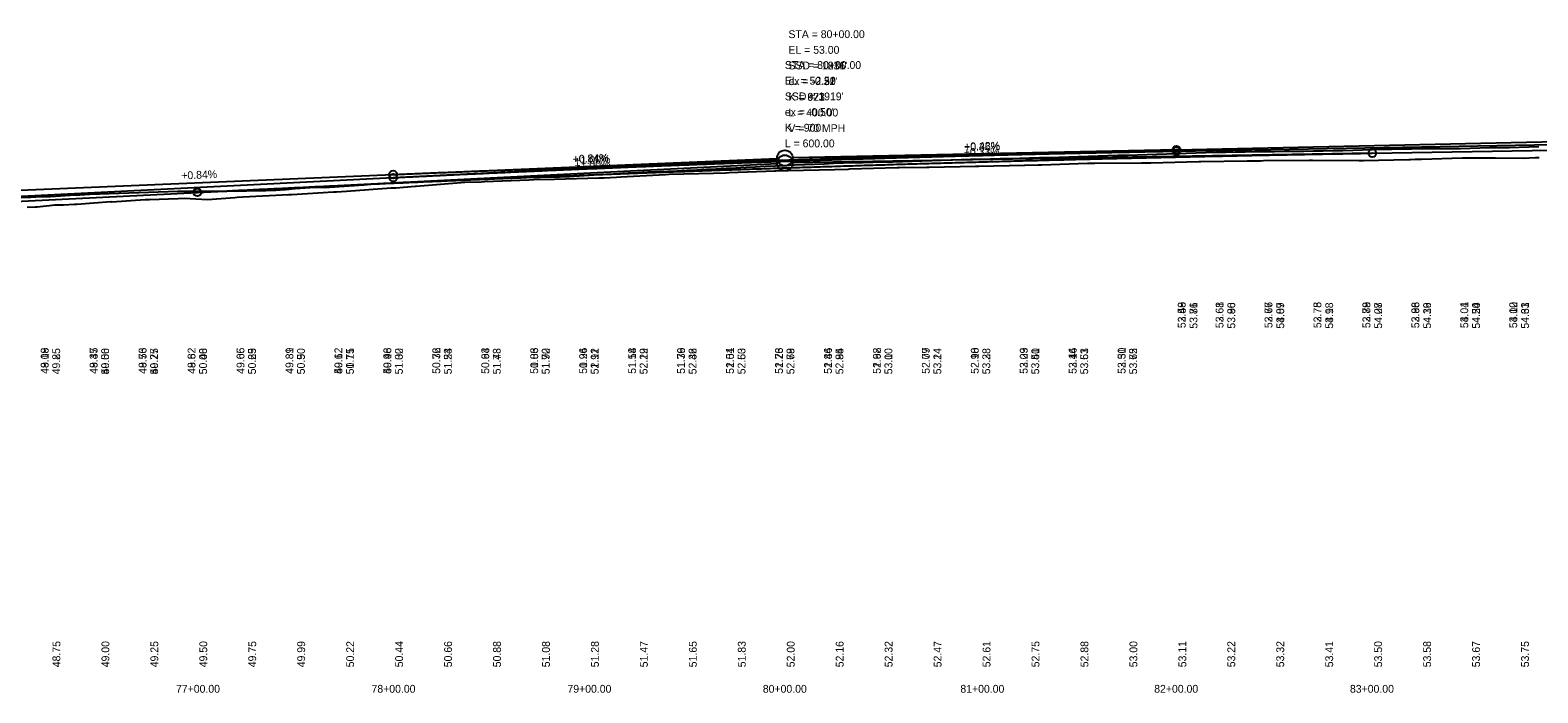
# Model space of a CAD drawing. Extents: x 3880794 to 3915434, y 287517 to 300173.
# Drawn here: x 3888153 to 3888923, y 296520 to 296858 of the extents above; entities that cross this region are included whole.
import ezdxf

# ---------------------------------------------------------------- set-up
doc = ezdxf.new("R2010")
doc.units = 0
for name, color, linetype in [('Level 1', 7, 'Continuous'), ('Level 2', 7, 'Continuous'), ('Level 30', 7, 'Continuous'), ('Level 31', 7, 'Continuous'), ('Level 32', 7, 'Continuous')]:
    doc.layers.add(name, color=color, linetype=linetype)

msp = doc.modelspace()

# ---------------------------------------------------------------- linework, layer by layer
at = {"layer": 'Level 1'}
for p, q in [((3888738.3, 296796.31), (3889688.3, 296813.2)), ((3888838.3, 296795.26), (3889488.3, 296806.09)), ((3888338.3, 296782.76), (3888534.3, 296792.56)), ((3888738.3, 296796.31), (3888542.3, 296792.83)), ((3888838.3, 296795.26), (3888542.3, 296790.32)), ((3888238.3, 296775.26), (3888534.3, 296790.06)), ((3888138.3, 296772.76), (3888338.3, 296782.76)), ((3888138.3, 296770.26), (3888238.3, 296775.26))]:
    msp.add_line(p, q, dxfattribs=at)
for points in [[(3888213.77, 296771.54), (3888228.46, 296772.14), (3888231.56, 296772.27), (3888243.46, 296771.57), (3888257.41, 296772.69), (3888258.68, 296772.75), (3888261.5, 296772.9), (3888284.97, 296774.13), (3888286.46, 296774.17), (3888307.75, 296775.47), (3888309.37, 296775.58), (3888314.47, 296775.93), (3888337.33, 296777.49), (3888339.57, 296777.64), (3888349.44, 296778.45), (3888350.03, 296778.49), (3888372.84, 296780.35), (3888374.91, 296780.39), (3888383.28, 296780.69), (3888384.96, 296780.85), (3888407.59, 296781.69), (3888410.04, 296781.81), (3888420.58, 296782.06), (3888443.34, 296782.6), (3888445.58, 296782.64), (3888446.03, 296782.65), (3888452.37, 296783.02), (3888454.51, 296783.14), (3888477.27, 296784.45), (3888479.27, 296784.48), (3888501.82, 296785.05), (3888508.1, 296785.3), (3888509.82, 296785.34), (3888533.14, 296786.26), (3888533.67, 296786.28), (3888538.47, 296786.39), (3888539.94, 296786.43), (3888563.67, 296786.97), (3888570.71, 296787.17), (3888571.55, 296787.22), (3888595.63, 296787.88), (3888596.7, 296787.91), (3888610.74, 296788.16), (3888611.98, 296788.17), (3888635.7, 296788.6), (3888637.29, 296788.63), (3888660.48, 296789.14), (3888660.86, 296789.15), (3888667.71, 296789.36), (3888669.32, 296789.38), (3888692.9, 296790.11), (3888695.23, 296790.13), (3888696.68, 296790.12), (3888720.41, 296790.3), (3888724.32, 296790.39), (3888725.18, 296790.4), (3888749.66, 296790.95), (3888750.77, 296790.97), (3888774.45, 296791.36), (3888781.24, 296791.42), (3888782.73, 296791.49), (3888806.24, 296791.72), (3888807.7, 296791.71), (3888831.41, 296791.52), (3888831.99, 296791.58), (3888832.85, 296791.6), (3888833.74, 296791.58), (3888856.89, 296792.08), (3888857.87, 296792.1), (3888860.16, 296792.19), (3888861.46, 296792.18), (3888863.36, 296792.15), (3888884.3, 296792.87), (3888887.58, 296792.95), (3888894.96, 296792.83), (3888901.15, 296792.94), (3888915.31, 296792.72), (3888921.69, 296793.05), (3888923.47, 296792.97)], [(3888151.4, 296767.63), (3888155.49, 296767.82), (3888156.52, 296767.94), (3888161.02, 296768.35), (3888162.78, 296768.59), (3888165.44, 296768.96), (3888167.71, 296768.85), (3888168.39, 296768.88), (3888169.57, 296768.85), (3888169.87, 296768.86), (3888175.48, 296769.17), (3888175.94, 296769.22), (3888176.69, 296769.29), (3888194.04, 296770.52), (3888194.67, 296770.46), (3888211.62, 296771.54), (3888213.77, 296771.54)]]:
    msp.add_lwpolyline(points, dxfattribs=at)
for centre in [(3888538.3, 296792.76), (3888538.3, 296790.26)]:
    msp.add_circle(centre, 4, dxfattribs=at)
for points in [[(3888238.3, 296775.26), (3888250.3, 296775.85), (3888262.3, 296776.44), (3888274.3, 296777.02), (3888286.3, 296777.59), (3888298.3, 296778.16), (3888310.3, 296778.71), (3888322.3, 296779.26), (3888334.3, 296779.8), (3888346.3, 296780.33), (3888358.3, 296780.86), (3888370.3, 296781.37), (3888382.3, 296781.88), (3888394.3, 296782.38), (3888406.3, 296782.87), (3888418.3, 296783.36), (3888430.3, 296783.83), (3888442.3, 296784.3), (3888454.3, 296784.76), (3888466.3, 296785.21), (3888478.3, 296785.66), (3888490.3, 296786.09), (3888502.3, 296786.52), (3888514.3, 296786.94), (3888526.3, 296787.35), (3888538.3, 296787.76), (3888550.3, 296788.15), (3888562.3, 296788.54), (3888574.3, 296788.92), (3888586.3, 296789.29), (3888598.3, 296789.66), (3888610.3, 296790.01), (3888622.3, 296790.36), (3888634.3, 296790.7), (3888646.3, 296791.03), (3888658.3, 296791.36), (3888670.3, 296791.67), (3888682.3, 296791.98), (3888694.3, 296792.28), (3888706.3, 296792.57), (3888718.3, 296792.86), (3888730.3, 296793.13), (3888742.3, 296793.4), (3888754.3, 296793.66), (3888766.3, 296793.91), (3888778.3, 296794.16), (3888790.3, 296794.39), (3888802.3, 296794.62), (3888814.3, 296794.84), (3888826.3, 296795.05), (3888838.3, 296795.26)], [(3888338.3, 296782.76), (3888346.3, 296783.15), (3888354.3, 296783.55), (3888362.3, 296783.93), (3888370.3, 296784.32), (3888378.3, 296784.69), (3888386.3, 296785.06), (3888394.3, 296785.43), (3888402.3, 296785.79), (3888410.3, 296786.15), (3888418.3, 296786.5), (3888426.3, 296786.85), (3888434.3, 296787.19), (3888442.3, 296787.52), (3888450.3, 296787.85), (3888458.3, 296788.18), (3888466.3, 296788.5), (3888474.3, 296788.81), (3888482.3, 296789.12), (3888490.3, 296789.43), (3888498.3, 296789.73), (3888506.3, 296790.02), (3888514.3, 296790.31), (3888522.3, 296790.59), (3888530.3, 296790.87), (3888538.3, 296791.15), (3888546.3, 296791.41), (3888554.3, 296791.68), (3888562.3, 296791.94), (3888570.3, 296792.19), (3888578.3, 296792.44), (3888586.3, 296792.68), (3888594.3, 296792.92), (3888602.3, 296793.15), (3888610.3, 296793.38), (3888618.3, 296793.6), (3888626.3, 296793.82), (3888634.3, 296794.03), (3888642.3, 296794.23), (3888650.3, 296794.44), (3888658.3, 296794.63), (3888666.3, 296794.82), (3888674.3, 296795.01), (3888682.3, 296795.19), (3888690.3, 296795.37), (3888698.3, 296795.54), (3888706.3, 296795.7), (3888714.3, 296795.86), (3888722.3, 296796.02), (3888730.3, 296796.17), (3888738.3, 296796.31)]]:
    msp.add_spline(points, degree=3, dxfattribs=at)
at = {"layer": 'Level 2'}
for p, q in [((3888738.3, 296797.04), (3889538.3, 296814.17)), ((3888338.3, 296784.36), (3888534.3, 296792.59)), ((3888738.3, 296797.04), (3888542.3, 296792.84)), ((3886763.3, 296718.25), (3888338.3, 296784.36))]:
    msp.add_line(p, q, dxfattribs=at)
for points in [[(3888538.3, 296789.05), (3888543.3, 296789.24), (3888548.3, 296789.43), (3888553.3, 296789.64), (3888558.3, 296789.86), (3888563.3, 296790.08), (3888568.3, 296790.26), (3888573.3, 296790.45), (3888578.3, 296790.52), (3888583.3, 296790.65), (3888588.3, 296790.86), (3888593.3, 296790.91), (3888598.3, 296790.95), (3888603.3, 296791.11), (3888608.3, 296791.36), (3888613.3, 296791.59), (3888618.3, 296791.73), (3888623.3, 296791.87), (3888628.3, 296791.99), (3888633.3, 296792.12), (3888638.3, 296792.26), (3888643.3, 296792.39), (3888648.3, 296792.53), (3888653.3, 296792.6), (3888658.3, 296792.75), (3888663.3, 296792.92), (3888668.3, 296793.03), (3888673.3, 296793.1), (3888678.3, 296793.19), (3888683.3, 296793.36), (3888688.3, 296793.54), (3888693.3, 296793.7), (3888698.3, 296793.85), (3888703.3, 296794), (3888708.3, 296794.16), (3888713.3, 296794.32), (3888718.3, 296794.49), (3888723.3, 296794.66), (3888728.3, 296794.82), (3888733.3, 296794.99), (3888738.3, 296795.15), (3888743.3, 296795.32), (3888748.3, 296795.48), (3888753.3, 296795.64), (3888758.3, 296795.75), (3888763.3, 296795.83), (3888768.3, 296795.92), (3888773.3, 296796), (3888778.3, 296796.09), (3888783.3, 296796.05), (3888788.3, 296796.13), (3888793.3, 296796.21), (3888798.3, 296796.26), (3888803.3, 296796.31), (3888808.3, 296796.38), (3888813.3, 296796.48), (3888818.3, 296796.6), (3888823.3, 296796.7), (3888828.3, 296796.8), (3888833.3, 296796.96), (3888838.3, 296797.19), (3888843.3, 296797.3), (3888848.3, 296797.38), (3888853.3, 296797.47), (3888858.3, 296797.52), (3888863.3, 296797.57), (3888868.3, 296797.62), (3888873.3, 296797.67), (3888878.3, 296797.69), (3888883.3, 296797.69), (3888888.3, 296797.82), (3888893.3, 296797.95), (3888898.3, 296798.09), (3888903.3, 296798.11), (3888908.3, 296798.21), (3888913.3, 296798.37), (3888918.3, 296798.55), (3888923.3, 296798.74)], [(3888148.3, 296772.61), (3888153.3, 296772.86), (3888158.3, 296773.1), (3888163.3, 296773.21), (3888168.3, 296773.48), (3888173.3, 296773.74), (3888178.3, 296774.02), (3888183.3, 296774.31), (3888188.3, 296774.49), (3888193.3, 296774.66), (3888198.3, 296774.84), (3888203.3, 296775.01), (3888208.3, 296775.2), (3888213.3, 296775.39), (3888218.3, 296775.59), (3888223.3, 296775.77), (3888228.3, 296775.85), (3888233.3, 296775.87), (3888238.3, 296775.88), (3888243.3, 296775.9), (3888248.3, 296775.91), (3888253.3, 296775.93), (3888258.3, 296775.98), (3888263.3, 296776.08), (3888268.3, 296776.17), (3888273.3, 296776.27), (3888278.3, 296776.37), (3888283.3, 296776.77), (3888288.3, 296777.2), (3888293.3, 296777.58), (3888298.3, 296777.96), (3888303.3, 296777.71), (3888308.3, 296778.12), (3888313.3, 296778.36), (3888318.3, 296778.69), (3888323.3, 296779.16), (3888328.3, 296779.63), (3888333.3, 296779.92), (3888338.3, 296780.16), (3888343.3, 296780.39), (3888348.3, 296780.64), (3888353.3, 296780.88), (3888358.3, 296781.12), (3888363.3, 296781.36), (3888368.3, 296781.6), (3888373.3, 296781.84), (3888378.3, 296782.08), (3888383.3, 296782.27), (3888388.3, 296782.43), (3888393.3, 296782.54), (3888398.3, 296782.63), (3888403.3, 296782.79), (3888408.3, 296782.95), (3888413.3, 296783.05), (3888418.3, 296783.13), (3888423.3, 296783.22), (3888428.3, 296783.43), (3888433.3, 296783.73), (3888438.3, 296784.05), (3888443.3, 296784.31), (3888448.3, 296784.52), (3888453.3, 296784.81), (3888458.3, 296785.14), (3888463.3, 296785.46), (3888468.3, 296785.71), (3888473.3, 296785.91), (3888478.3, 296786.11), (3888483.3, 296786.3), (3888488.3, 296786.55), (3888493.3, 296786.8), (3888498.3, 296787.05), (3888503.3, 296787.32), (3888508.3, 296787.57), (3888513.3, 296787.82), (3888518.3, 296788.08), (3888523.3, 296788.34), (3888528.3, 296788.61), (3888533.3, 296788.83), (3888538.3, 296789.05)]]:
    msp.add_lwpolyline(points, dxfattribs=at)
for centre, radius in [((3888538.3, 296792.76), 4), ((3888738.3, 296797.04), 2), ((3888338.3, 296784.36), 2)]:
    msp.add_circle(centre, radius, dxfattribs=at)
msp.add_spline([(3888338.3, 296784.36), (3888346.3, 296784.7), (3888354.3, 296785.03), (3888362.3, 296785.35), (3888370.3, 296785.68), (3888378.3, 296786), (3888386.3, 296786.32), (3888394.3, 296786.63), (3888402.3, 296786.94), (3888410.3, 296787.25), (3888418.3, 296787.56), (3888426.3, 296787.86), (3888434.3, 296788.15), (3888442.3, 296788.45), (3888450.3, 296788.74), (3888458.3, 296789.03), (3888466.3, 296789.31), (3888474.3, 296789.6), (3888482.3, 296789.87), (3888490.3, 296790.15), (3888498.3, 296790.42), (3888506.3, 296790.69), (3888514.3, 296790.95), (3888522.3, 296791.22), (3888530.3, 296791.47), (3888538.3, 296791.73), (3888546.3, 296791.98), (3888554.3, 296792.23), (3888562.3, 296792.47), (3888570.3, 296792.72), (3888578.3, 296792.96), (3888586.3, 296793.19), (3888594.3, 296793.42), (3888602.3, 296793.65), (3888610.3, 296793.88), (3888618.3, 296794.1), (3888626.3, 296794.32), (3888634.3, 296794.54), (3888642.3, 296794.75), (3888650.3, 296794.96), (3888658.3, 296795.16), (3888666.3, 296795.37), (3888674.3, 296795.56), (3888682.3, 296795.76), (3888690.3, 296795.95), (3888698.3, 296796.14), (3888706.3, 296796.33), (3888714.3, 296796.51), (3888722.3, 296796.69), (3888730.3, 296796.87), (3888738.3, 296797.04)], degree=3, dxfattribs=at)
at = {"layer": 'Level 31'}
for centre in [(3888738.3, 296796.31), (3888838.3, 296795.26), (3888238.3, 296775.26), (3888338.3, 296782.76)]:
    msp.add_circle(centre, 2, dxfattribs=at)

# ---------------------------------------------------------------- texts
at = {"layer": 'Level 2'}
for s, p in [('STA = 80+00.00', (3888540.14, 296854.02)), ('EL = 53.00', (3888540.14, 296846.02)), ("SSD = 1816'", (3888540.14, 296838.02)), ("ex = -0.21'", (3888540.14, 296830.02)), ('K = 973', (3888540.14, 296822.02)), ('L = 400.00', (3888540.14, 296814.02)), ('V = 70 MPH', (3888540.14, 296806.02)), ('77+00.00', (3888227.37, 296519.76)), ('78+00.00', (3888327.21, 296519.76)), ('79+00.00', (3888427.27, 296519.76)), ('80+00.00', (3888527.05, 296519.76)), ('81+00.00', (3888627.94, 296519.76)), ('82+00.00', (3888726.93, 296519.76)), ('83+00.00', (3888826.9, 296519.76))]:
    msp.add_text(s, height=4, dxfattribs=at).set_placement(p)
for s, rotation, p in [('+0.43%', 1.2269, (3888629.92, 296796.72)), ('+0.84%', 2.4036, (3888429.98, 296790.21)), ('+0.84%', 2.4036, (3888430.15, 296790.22)), ('+0.84%', 2.4036, (3888230.15, 296781.83)), ('53.86', 90, (3888748.99, 296705.66)), ('53.96', 90, (3888768.3, 296705.66)), ('54.07', 90, (3888793.3, 296705.66)), ('54.18', 90, (3888818.3, 296705.66)), ('54.28', 90, (3888843.3, 296705.66)), ('54.39', 90, (3888868.3, 296705.66)), ('54.50', 90, (3888893.3, 296705.66)), ('54.61', 90, (3888918.3, 296705.66)), ('49.85', 90, (3888168.18, 296682.34)), ('50.06', 90, (3888193.18, 296682.34)), ('50.27', 90, (3888218.18, 296682.34)), ('50.48', 90, (3888243.18, 296682.34)), ('50.69', 90, (3888268.18, 296682.34)), ('50.90', 90, (3888293.18, 296682.34)), ('51.11', 90, (3888318.18, 296682.34)), ('51.32', 90, (3888343.18, 296682.34)), ('51.53', 90, (3888368.18, 296682.34)), ('51.73', 90, (3888393.18, 296682.34)), ('51.92', 90, (3888418.18, 296682.34)), ('52.11', 90, (3888443.18, 296682.34)), ('52.29', 90, (3888468.18, 296682.34)), ('52.46', 90, (3888493.18, 296682.34)), ('52.63', 90, (3888518.18, 296682.34)), ('52.79', 90, (3888543.18, 296682.34)), ('52.95', 90, (3888568.18, 296682.34)), ('53.10', 90, (3888593.18, 296682.34)), ('53.24', 90, (3888618.18, 296682.34)), ('53.38', 90, (3888643.18, 296682.34)), ('53.51', 90, (3888668.18, 296682.34)), ('53.63', 90, (3888693.18, 296682.34)), ('53.75', 90, (3888718.18, 296682.34))]:
    msp.add_text(s, height=4, rotation=rotation, dxfattribs=at).set_placement(p)
at = {"layer": 'Level 30'}
for s, p in [('52.59', (3888742.99, 296705.91)), ('52.68', (3888762.3, 296705.91)), ('52.76', (3888787.3, 296705.91)), ('52.78', (3888812.3, 296705.91)), ('52.78', (3888837.3, 296705.91)), ('52.88', (3888862.3, 296705.91)), ('53.04', (3888887.3, 296705.91)), ('53.00', (3888912.3, 296705.91)), ('48.18', (3888162.3, 296682.58)), ('48.47', (3888187.3, 296682.58)), ('48.76', (3888212.3, 296682.58)), ('48.82', (3888237.3, 296682.58)), ('49.05', (3888262.3, 296682.58)), ('49.31', (3888287.3, 296682.58)), ('49.62', (3888312.3, 296682.58)), ('49.96', (3888337.3, 296682.58)), ('50.36', (3888362.3, 296682.58)), ('50.64', (3888387.3, 296682.58)), ('50.83', (3888412.3, 296682.58)), ('50.94', (3888437.3, 296682.58)), ('51.18', (3888462.3, 296682.58)), ('51.39', (3888487.3, 296682.58)), ('51.54', (3888512.3, 296682.58)), ('51.73', (3888537.3, 296682.58)), ('51.84', (3888562.3, 296682.58)), ('51.98', (3888587.3, 296682.58)), ('52.09', (3888612.3, 296682.58)), ('52.18', (3888637.3, 296682.58)), ('52.29', (3888662.3, 296682.58)), ('52.44', (3888687.3, 296682.58)), ('52.50', (3888712.3, 296682.58))]:
    msp.add_text(s, height=4, rotation=90, dxfattribs=at).set_placement(p)
for s, p in [('77+00.00', (3888227.37, 296519.76)), ('77+00.00', (3888227.37, 296519.76)), ('77+00.00', (3888227.37, 296519.76)), ('78+00.00', (3888327.21, 296519.76)), ('78+00.00', (3888327.21, 296519.76)), ('78+00.00', (3888327.21, 296519.76)), ('79+00.00', (3888427.27, 296519.76)), ('79+00.00', (3888427.27, 296519.76)), ('79+00.00', (3888427.27, 296519.76)), ('80+00.00', (3888527.05, 296519.76)), ('80+00.00', (3888527.05, 296519.76)), ('80+00.00', (3888527.05, 296519.76)), ('81+00.00', (3888627.94, 296519.76)), ('81+00.00', (3888627.94, 296519.76)), ('81+00.00', (3888627.94, 296519.76)), ('82+00.00', (3888726.93, 296519.76)), ('82+00.00', (3888726.93, 296519.76)), ('82+00.00', (3888726.93, 296519.76)), ('83+00.00', (3888826.9, 296519.76)), ('83+00.00', (3888826.9, 296519.76)), ('83+00.00', (3888826.9, 296519.76))]:
    msp.add_text(s, height=4, dxfattribs=at).set_placement(p)
at = {"layer": 'Level 31'}
for s, p in [('STA = 80+00.00', (3888540.14, 296854.02)), ('EL = 53.00', (3888540.14, 296846.02)), ('STA = 80+00.00', (3888538.3, 296838.26)), ("SSD = 1231'", (3888540.14, 296838.02)), ('EL = 52.50', (3888538.3, 296830.26)), ("ex = -0.32'", (3888540.14, 296830.02)), ("SSD = 1919'", (3888538.3, 296822.26)), ('K = 621', (3888540.14, 296822.02)), ("ex = -0.50'", (3888538.3, 296814.26)), ('L = 400.00', (3888540.14, 296814.02)), ('K = 900', (3888538.3, 296806.26)), ('V = 70 MPH', (3888540.14, 296806.02)), ('L = 600.00', (3888538.3, 296798.26))]:
    msp.add_text(s, height=4, dxfattribs=at).set_placement(p)
for s, rotation, p in [('+0.36%', 1.01848, (3888629.93, 296796.39)), ('+1.00%', 2.86241, (3888430.99, 296789.4)), ('+0.33%', 0.95484, (3888629.71, 296793.78)), ('+1.00%', 2.86241, (3888430.99, 296786.9)), ('53.71', 90, (3888748.99, 296705.66)), ('53.80', 90, (3888768.3, 296705.66)), ('53.89', 90, (3888793.3, 296705.66)), ('53.98', 90, (3888818.3, 296705.66)), ('54.07', 90, (3888843.3, 296705.66)), ('54.16', 90, (3888868.3, 296705.66)), ('54.24', 90, (3888893.3, 296705.66)), ('54.33', 90, (3888918.3, 296705.66)), ('49.25', 90, (3888168.18, 296682.34)), ('49.50', 90, (3888193.18, 296682.34)), ('49.75', 90, (3888218.18, 296682.34)), ('50.00', 90, (3888243.18, 296682.34)), ('50.25', 90, (3888268.18, 296682.34)), ('50.50', 90, (3888293.18, 296682.34)), ('50.75', 90, (3888318.18, 296682.34)), ('51.00', 90, (3888343.18, 296682.34)), ('51.24', 90, (3888368.18, 296682.34)), ('51.48', 90, (3888393.18, 296682.34)), ('51.70', 90, (3888418.18, 296682.34)), ('51.92', 90, (3888443.18, 296682.34)), ('52.12', 90, (3888468.18, 296682.34)), ('52.32', 90, (3888493.18, 296682.34)), ('52.50', 90, (3888518.18, 296682.34)), ('52.68', 90, (3888543.18, 296682.34)), ('52.84', 90, (3888568.18, 296682.34)), ('53.00', 90, (3888593.18, 296682.34)), ('53.14', 90, (3888618.18, 296682.34)), ('53.28', 90, (3888643.18, 296682.34)), ('53.40', 90, (3888668.18, 296682.34)), ('53.51', 90, (3888693.18, 296682.34)), ('53.62', 90, (3888718.18, 296682.34)), ('48.75', 90, (3888168.3, 296532.76)), ('49.00', 90, (3888193.3, 296532.76)), ('49.25', 90, (3888218.3, 296532.76)), ('49.50', 90, (3888243.3, 296532.76)), ('49.75', 90, (3888268.3, 296532.76)), ('49.99', 90, (3888293.3, 296532.76)), ('50.22', 90, (3888318.3, 296532.76)), ('50.44', 90, (3888343.3, 296532.76)), ('50.66', 90, (3888368.3, 296532.76)), ('50.88', 90, (3888393.3, 296532.76)), ('51.08', 90, (3888418.3, 296532.76)), ('51.28', 90, (3888443.3, 296532.76)), ('51.47', 90, (3888468.3, 296532.76)), ('51.65', 90, (3888493.3, 296532.76)), ('51.83', 90, (3888518.3, 296532.76)), ('52.00', 90, (3888543.3, 296532.76)), ('52.16', 90, (3888568.3, 296532.76)), ('52.32', 90, (3888593.3, 296532.76)), ('52.47', 90, (3888618.3, 296532.76)), ('52.61', 90, (3888643.3, 296532.76)), ('52.75', 90, (3888668.3, 296532.76)), ('52.88', 90, (3888693.3, 296532.76)), ('53.00', 90, (3888718.3, 296532.76)), ('53.11', 90, (3888743.3, 296532.76)), ('53.22', 90, (3888768.3, 296532.76)), ('53.32', 90, (3888793.3, 296532.76)), ('53.41', 90, (3888818.3, 296532.76)), ('53.50', 90, (3888843.3, 296532.76)), ('53.58', 90, (3888868.3, 296532.76)), ('53.67', 90, (3888893.3, 296532.76)), ('53.75', 90, (3888918.3, 296532.76))]:
    msp.add_text(s, height=4, rotation=rotation, dxfattribs=at).set_placement(p)
at = {"layer": 'Level 32'}
for s, p in [('53.48', (3888742.99, 296705.91)), ('53.61', (3888762.3, 296705.91)), ('53.67', (3888787.3, 296705.91)), ('53.75', (3888812.3, 296705.91)), ('53.89', (3888837.3, 296705.91)), ('53.96', (3888862.3, 296705.91)), ('54.01', (3888887.3, 296705.91)), ('54.12', (3888912.3, 296705.91)), ('49.09', (3888162.3, 296682.58)), ('49.35', (3888187.3, 296682.58)), ('49.53', (3888212.3, 296682.58)), ('49.62', (3888237.3, 296682.58)), ('49.66', (3888262.3, 296682.58)), ('49.89', (3888287.3, 296682.58)), ('50.12', (3888312.3, 296682.58)), ('50.48', (3888337.3, 296682.58)), ('50.72', (3888362.3, 296682.58)), ('50.93', (3888387.3, 296682.58)), ('51.06', (3888412.3, 296682.58)), ('51.26', (3888437.3, 296682.58)), ('51.54', (3888462.3, 296682.58)), ('51.76', (3888487.3, 296682.58)), ('52.01', (3888512.3, 296682.58)), ('52.26', (3888537.3, 296682.58)), ('52.46', (3888562.3, 296682.58)), ('52.62', (3888587.3, 296682.58)), ('52.77', (3888612.3, 296682.58)), ('52.90', (3888637.3, 296682.58)), ('53.03', (3888662.3, 296682.58)), ('53.16', (3888687.3, 296682.58)), ('53.31', (3888712.3, 296682.58))]:
    msp.add_text(s, height=4, rotation=90, dxfattribs=at).set_placement(p)

doc.saveas('drawing.dxf')
